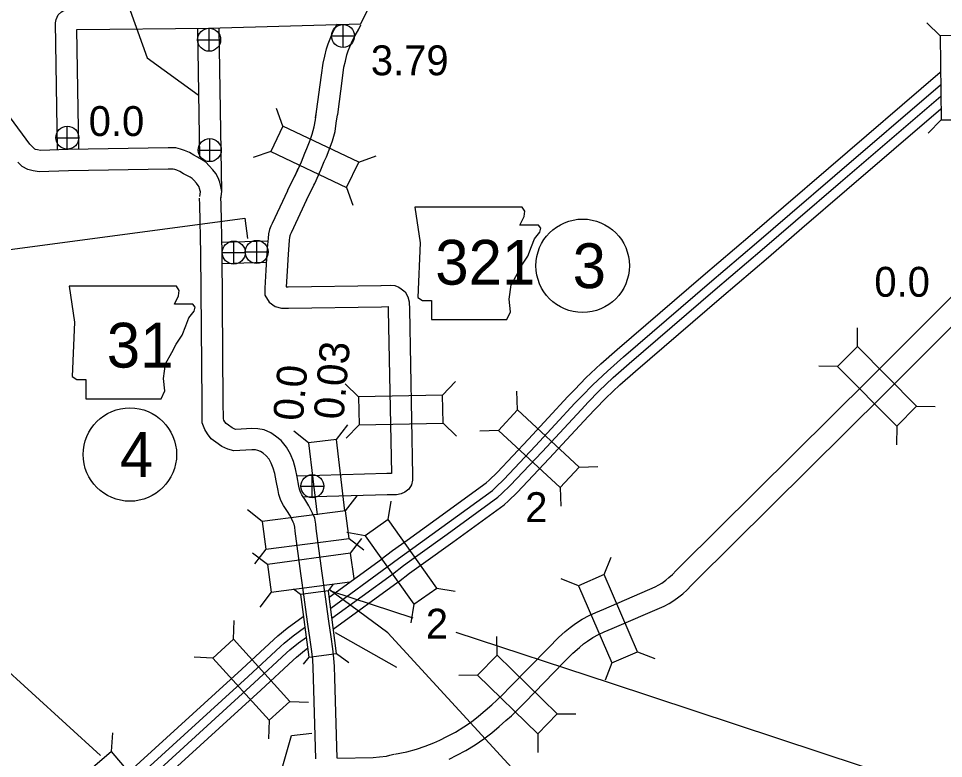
# Model space of a CAD drawing. Extents: x -939622 to -934222, y 1383701 to 1385301.
# Drawn here: x -936410.42 to -936371.19, y 1384450.69 to 1384482.07 of the extents above; entities that cross this region are included whole.
import ezdxf

# ---------------------------------------------------------------- set-up
doc = ezdxf.new("R2010")
doc.units = 0
for name, color, linetype in [('10', 7, 'Continuous'), ('15', 7, 'Continuous'), ('20', 7, 'Continuous'), ('21', 7, 'Continuous'), ('22', 7, 'Continuous'), ('25', 7, 'Continuous'), ('26', 7, 'Continuous'), ('27', 7, 'Continuous')]:
    doc.layers.add(name, color=color, linetype=linetype)

msp = doc.modelspace()

# ---------------------------------------------------------------- linework, layer by layer
at = {"layer": '10'}
for points in [[(-936408.764, 1384476.532), (-936408.845, 1384481.893), (-936408.816, 1384482.034), (-936408.737, 1384482.223), (-936408.59, 1384482.354), (-936408.454, 1384482.435), (-936408.281, 1384482.483), (-936408.107, 1384482.505), (-936402.372, 1384482.567), (-936396.465, 1384482.734), (-936396.297, 1384483.081), (-936396.201, 1384483.299), (-936396.082, 1384483.511), (-936395.97, 1384483.682), (-936395.874, 1384483.83), (-936395.784, 1384483.937)], [(-936407.864, 1384476.559), (-936407.941, 1384481.607), (-936402.355, 1384481.667), (-936395.894, 1384481.85), (-936395.48, 1384482.702), (-936395.394, 1384482.897), (-936395.312, 1384483.044), (-936395.216, 1384483.191), (-936395.15, 1384483.293), (-936395.097, 1384483.355)], [(-936402.723, 1384476.207), (-936402.806, 1384481.616)], [(-936401.801, 1384474.736), (-936401.906, 1384481.644)], [(-936397.816, 1384477.856), (-936397.773, 1384478.133), (-936397.574, 1384479.667), (-936397.502, 1384480.173), (-936397.431, 1384480.473), (-936397.355, 1384480.779), (-936397.279, 1384481.002), (-936397.201, 1384481.204), (-936397.073, 1384481.523), (-936396.921, 1384481.793), (-936396.896, 1384481.836)], [(-936396.886, 1384477.98), (-936396.882, 1384478.005), (-936396.682, 1384479.546), (-936396.616, 1384480.006), (-936396.556, 1384480.261), (-936396.491, 1384480.524), (-936396.432, 1384480.695), (-936396.363, 1384480.875), (-936396.26, 1384481.133), (-936396.141, 1384481.344), (-936395.979, 1384481.618), (-936395.899, 1384481.805)], [(-936401.841, 1384474.406), (-936401.795, 1384474.736), (-936401.831, 1384474.949), (-936401.877, 1384475.127), (-936401.944, 1384475.315), (-936402.049, 1384475.492), (-936402.179, 1384475.66), (-936402.33, 1384475.828), (-936402.475, 1384475.975), (-936402.655, 1384476.098), (-936402.822, 1384476.196), (-936402.985, 1384476.28), (-936403.172, 1384476.387), (-936403.377, 1384476.48), (-936403.544, 1384476.535), (-936403.748, 1384476.584), (-936404.069, 1384476.587), (-936408.318, 1384476.516), (-936409.479, 1384476.473), (-936409.613, 1384476.498), (-936409.704, 1384476.518), (-936409.726, 1384476.53), (-936409.813, 1384476.615), (-936409.932, 1384476.74), (-936410.093, 1384476.96), (-936411.939, 1384479.451)], [(-936398.69, 1384475.404), (-936398.658, 1384475.467), (-936398.42, 1384475.996), (-936398.277, 1384476.367), (-936398.186, 1384476.558), (-936398.051, 1384476.917), (-936397.965, 1384477.164), (-936397.874, 1384477.478), (-936397.829, 1384477.775), (-936397.775, 1384478.12)], [(-936397.886, 1384474.998), (-936397.846, 1384475.079), (-936397.589, 1384475.649), (-936397.449, 1384476.012), (-936397.357, 1384476.205), (-936397.205, 1384476.61), (-936397.107, 1384476.89), (-936396.993, 1384477.285), (-936396.94, 1384477.638), (-936396.886, 1384477.98)], [(-936402.733, 1384474.529), (-936402.706, 1384474.723), (-936402.712, 1384474.761), (-936402.739, 1384474.864), (-936402.763, 1384474.932), (-936402.795, 1384474.986), (-936402.87, 1384475.083), (-936402.984, 1384475.21), (-936403.055, 1384475.28), (-936403.137, 1384475.337), (-936403.256, 1384475.407), (-936403.416, 1384475.489), (-936403.582, 1384475.584), (-936403.705, 1384475.64), (-936403.792, 1384475.669), (-936403.86, 1384475.685), (-936404.066, 1384475.687), (-936408.294, 1384475.616), (-936409.544, 1384475.571), (-936409.79, 1384475.615), (-936410.019, 1384475.666), (-936410.264, 1384475.797), (-936410.454, 1384475.983)], [(-936399.008, 1384474.774), (-936398.658, 1384475.467), (-936398.551, 1384475.705)], [(-936398.205, 1384474.368), (-936397.886, 1384474.998)], [(-936399.014, 1384474.761), (-936399.663, 1384473.374), (-936399.715, 1384473.27), (-936399.774, 1384473.119), (-936399.814, 1384472.94), (-936399.835, 1384472.757), (-936399.867, 1384472.328), (-936399.88, 1384472.136), (-936399.927, 1384471.406), (-936399.966, 1384470.643), (-936399.969, 1384470.339), (-936399.79, 1384470.048), (-936399.534, 1384469.858), (-936399.268, 1384469.794), (-936398.972, 1384469.794), (-936395.03, 1384469.847)], [(-936398.295, 1384457.43), (-936398.441, 1384458.532), (-936398.682, 1384460.326), (-936398.704, 1384460.496), (-936398.725, 1384460.626), (-936398.765, 1384460.72), (-936398.888, 1384460.962), (-936399.043, 1384461.21), (-936399.177, 1384461.419), (-936399.29, 1384461.636), (-936399.376, 1384461.886), (-936399.41, 1384462.063), (-936399.488, 1384462.46), (-936399.554, 1384462.777), (-936399.613, 1384463.005), (-936399.697, 1384463.209), (-936399.794, 1384463.385), (-936399.912, 1384463.528), (-936400.047, 1384463.633), (-936400.16, 1384463.711), (-936400.265, 1384463.757), (-936400.374, 1384463.777), (-936400.523, 1384463.784), (-936401.29, 1384463.744), (-936401.536, 1384463.81), (-936401.799, 1384463.924), (-936402.048, 1384464.102), (-936402.241, 1384464.245), (-936402.404, 1384464.454), (-936402.52, 1384464.646), (-936402.628, 1384464.922), (-936402.634, 1384465.803), (-936402.685, 1384472.112), (-936402.729, 1384474.165), (-936402.737, 1384474.456)], [(-936397.403, 1384457.547), (-936397.549, 1384458.651), (-936397.789, 1384460.443), (-936397.813, 1384460.627), (-936397.855, 1384460.88), (-936397.949, 1384461.101), (-936398.104, 1384461.405), (-936398.281, 1384461.69), (-936398.397, 1384461.871), (-936398.461, 1384461.993), (-936398.504, 1384462.118), (-936398.526, 1384462.234), (-936398.606, 1384462.639), (-936398.677, 1384462.981), (-936398.758, 1384463.291), (-936398.885, 1384463.599), (-936399.046, 1384463.892), (-936399.281, 1384464.178), (-936399.514, 1384464.358), (-936399.718, 1384464.5), (-936400.001, 1384464.624), (-936400.272, 1384464.673), (-936400.525, 1384464.685), (-936401.196, 1384464.65), (-936401.239, 1384464.662), (-936401.353, 1384464.712), (-936401.519, 1384464.83), (-936401.607, 1384464.896), (-936401.661, 1384464.964), (-936401.709, 1384465.044), (-936401.729, 1384465.096), (-936401.734, 1384465.809), (-936401.785, 1384472.126), (-936401.829, 1384474.186), (-936401.837, 1384474.479)], [(-936398.199, 1384474.38), (-936398.852, 1384472.983), (-936398.892, 1384472.904), (-936398.911, 1384472.855), (-936398.925, 1384472.792), (-936398.938, 1384472.673), (-936398.969, 1384472.264), (-936398.982, 1384472.076), (-936399.029, 1384471.354), (-936399.062, 1384470.694), (-936398.978, 1384470.694), (-936395.042, 1384470.747)], [(-936401.779, 1384472.583), (-936399.858, 1384472.64)], [(-936401.775, 1384471.683), (-936399.938, 1384471.737)], [(-936395.052, 1384470.747), (-936394.639, 1384470.762), (-936394.463, 1384470.752), (-936394.293, 1384470.673), (-936394.192, 1384470.61), (-936394.025, 1384470.476), (-936393.905, 1384470.267), (-936393.851, 1384470.057), (-936393.837, 1384469.734), (-936393.702, 1384462.691), (-936393.705, 1384462.488), (-936393.754, 1384462.299), (-936393.867, 1384462.111), (-936394.034, 1384461.992), (-936394.188, 1384461.916), (-936394.39, 1384461.873), (-936394.783, 1384461.876)], [(-936394.469, 1384450.878), (-936393.948, 1384450.975), (-936393.534, 1384451.082), (-936393.167, 1384451.214), (-936392.8, 1384451.357), (-936392.549, 1384451.469), (-936392.254, 1384451.628), (-936391.89, 1384451.816), (-936391.537, 1384452.034), (-936391.206, 1384452.254), (-936390.906, 1384452.486), (-936390.62, 1384452.725), (-936390.344, 1384452.973), (-936390.128, 1384453.164), (-936389.882, 1384453.41), (-936389.578, 1384453.719), (-936387.943, 1384455.392), (-936387.52, 1384455.817), (-936387.227, 1384456.074), (-936387.025, 1384456.254), (-936386.791, 1384456.421), (-936386.514, 1384456.595), (-936386.222, 1384456.758), (-936385.934, 1384456.883), (-936385.59, 1384457.032), (-936383.413, 1384457.974), (-936383.254, 1384458.052), (-936383.129, 1384458.13), (-936382.97, 1384458.25), (-936382.834, 1384458.362), (-936382.683, 1384458.5), (-936382.523, 1384458.658), (-936382.354, 1384458.832), (-936374.322, 1384466.793), (-936370.847, 1384470.269)], [(-936395.019, 1384469.848), (-936394.743, 1384469.857), (-936394.737, 1384469.707), (-936394.604, 1384462.775), (-936394.776, 1384462.776)], [(-936392.153, 1384450.66), (-936391.833, 1384450.832), (-936391.446, 1384451.033), (-936391.051, 1384451.276), (-936390.681, 1384451.522), (-936390.342, 1384451.785), (-936390.031, 1384452.045), (-936389.745, 1384452.301), (-936389.511, 1384452.508), (-936389.243, 1384452.776), (-936388.936, 1384453.088), (-936387.302, 1384454.76), (-936386.904, 1384455.16), (-936386.63, 1384455.401), (-936386.462, 1384455.55), (-936386.291, 1384455.673), (-936386.056, 1384455.82), (-936385.822, 1384455.95), (-936385.576, 1384456.057), (-936385.233, 1384456.206), (-936383.036, 1384457.156), (-936382.817, 1384457.264), (-936382.618, 1384457.388), (-936382.413, 1384457.543), (-936382.244, 1384457.681), (-936382.062, 1384457.848), (-936381.884, 1384458.024), (-936381.715, 1384458.198), (-936373.687, 1384466.156), (-936370.208, 1384469.636)], [(-936394.792, 1384462.776), (-936398.586, 1384462.669)], [(-936394.767, 1384461.876), (-936398.37, 1384461.775)], [(-936396.896, 1384450.707), (-936395.372, 1384450.733), (-936395.102, 1384450.757), (-936394.815, 1384450.792), (-936394.67, 1384450.828), (-936394.497, 1384450.872)]]:
    msp.add_lwpolyline(points, dxfattribs=at)
at = {"layer": '15'}
for points in [[(-936376.062, 1384475.732), (-936371.325, 1384479.792)], [(-936375.793, 1384475.419), (-936371.313, 1384479.259)], [(-936375.549, 1384475.134), (-936371.295, 1384478.781)], [(-936375.281, 1384474.821), (-936371.297, 1384478.236)], [(-936395.036, 1384459.141), (-936394.553, 1384459.511), (-936393.935, 1384459.949), (-936392.701, 1384460.841), (-936390.581, 1384462.385), (-936390.452, 1384462.499), (-936390.124, 1384462.819), (-936388.787, 1384464.237), (-936387.118, 1384466.038), (-936386.82, 1384466.345), (-936386.357, 1384466.828), (-936385.721, 1384467.427), (-936385.029, 1384468.031), (-936381.377, 1384471.173), (-936379.392, 1384472.869), (-936377.971, 1384474.089), (-936376.063, 1384475.731)], [(-936394.785, 1384458.814), (-936394.308, 1384459.179), (-936393.695, 1384459.614), (-936392.459, 1384460.507), (-936390.322, 1384462.063), (-936390.171, 1384462.197), (-936389.83, 1384462.53), (-936388.486, 1384463.956), (-936386.818, 1384465.754), (-936386.523, 1384466.058), (-936386.066, 1384466.535), (-936385.444, 1384467.122), (-936384.759, 1384467.719), (-936381.109, 1384470.86), (-936379.124, 1384472.556), (-936377.702, 1384473.777), (-936375.794, 1384475.418)], [(-936394.556, 1384458.516), (-936394.086, 1384458.877), (-936393.477, 1384459.309), (-936392.239, 1384460.203), (-936390.086, 1384461.771), (-936389.915, 1384461.923), (-936389.562, 1384462.267), (-936388.212, 1384463.7), (-936386.546, 1384465.496), (-936386.253, 1384465.798), (-936385.802, 1384466.269), (-936385.192, 1384466.844), (-936384.513, 1384467.436), (-936380.865, 1384470.576), (-936378.88, 1384472.271), (-936377.457, 1384473.492), (-936375.549, 1384475.134)], [(-936394.305, 1384458.189), (-936393.841, 1384458.545), (-936393.237, 1384458.973), (-936391.996, 1384459.869), (-936389.827, 1384461.449), (-936389.634, 1384461.621), (-936389.268, 1384461.977), (-936387.911, 1384463.418), (-936386.247, 1384465.212), (-936385.956, 1384465.512), (-936385.511, 1384465.976), (-936384.915, 1384466.538), (-936384.243, 1384467.124), (-936380.596, 1384470.262), (-936378.612, 1384471.957), (-936377.189, 1384473.179), (-936375.28, 1384474.822)], [(-936397.241, 1384457.533), (-936395.024, 1384459.15)], [(-936397.177, 1384457.069), (-936394.781, 1384458.816)], [(-936397.132, 1384456.638), (-936394.56, 1384458.513)], [(-936397.066, 1384456.175), (-936394.317, 1384458.18)], [(-936397.804, 1384450.675), (-936397.9, 1384454.089), (-936397.915, 1384454.55), (-936397.94, 1384454.874), (-936397.976, 1384455.235), (-936398.047, 1384455.728), (-936398.142, 1384456.393), (-936398.294, 1384457.423)], [(-936396.905, 1384450.702), (-936397.001, 1384454.116), (-936397.016, 1384454.6), (-936397.044, 1384454.953), (-936397.082, 1384455.343), (-936397.156, 1384455.857), (-936397.252, 1384456.523), (-936397.404, 1384457.554)], [(-936405.74, 1384450.113), (-936400.95, 1384454.474), (-936399.584, 1384455.745), (-936399.424, 1384455.894), (-936399.025, 1384456.22), (-936398.35, 1384456.72)], [(-936405.473, 1384449.798), (-936400.671, 1384454.171), (-936399.303, 1384455.443), (-936399.153, 1384455.583), (-936398.771, 1384455.894), (-936398.288, 1384456.253)], [(-936405.23, 1384449.512), (-936400.417, 1384453.895), (-936399.048, 1384455.168), (-936398.906, 1384455.3), (-936398.541, 1384455.598), (-936398.211, 1384455.843)], [(-936404.963, 1384449.198), (-936400.137, 1384453.591), (-936398.767, 1384454.866), (-936398.635, 1384454.989), (-936398.288, 1384455.273), (-936398.16, 1384455.367)]]:
    msp.add_lwpolyline(points, dxfattribs=at)
at = {"layer": '20'}
for p, q in [((-936371.326, 1384481.333), (-936371.892, 1384481.887)), ((-936399.208, 1384477.51), (-936399.472, 1384478.257)), ((-936371.288, 1384477.769), (-936371.843, 1384477.203)), ((-936399.719, 1384476.438), (-936400.466, 1384476.173)), ((-936395.991, 1384475.976), (-936395.244, 1384476.241)), ((-936396.502, 1384474.904), (-936396.237, 1384474.158)), ((-936374.837, 1384468.158), (-936374.834, 1384468.95)), ((-936375.681, 1384467.322), (-936376.473, 1384467.325)), ((-936395.999, 1384466.035), (-936396.569, 1384466.584)), ((-936392.435, 1384466.103), (-936391.886, 1384466.674)), ((-936389.252, 1384465.475), (-936389.281, 1384466.266)), ((-936372.328, 1384465.627), (-936371.536, 1384465.624)), ((-936396.936, 1384464.222), (-936396.446, 1384464.844)), ((-936395.976, 1384464.847), (-936396.525, 1384464.276)), ((-936392.413, 1384464.916), (-936391.842, 1384464.367)), ((-936373.172, 1384464.791), (-936373.175, 1384463.999)), ((-936398.116, 1384464.083), (-936398.738, 1384464.574)), ((-936390.059, 1384464.604), (-936390.851, 1384464.574)), ((-936396.936, 1384464.222), (-936398.116, 1384464.083)), ((-936398.116, 1384464.083), (-936397.756, 1384461.03)), ((-936396.579, 1384461.191), (-936396.936, 1384464.222)), ((-936386.638, 1384463.052), (-936385.847, 1384463.081)), ((-936387.446, 1384462.18), (-936387.416, 1384461.389)), ((-936396.543, 1384461.199), (-936396.058, 1384461.825)), ((-936394.743, 1384460.825), (-936394.61, 1384461.606)), ((-936400.078, 1384460.748), (-936400.705, 1384461.233)), ((-936395.712, 1384460.138), (-936396.493, 1384460.272)), ((-936396.332, 1384459.393), (-936395.852, 1384460.023)), ((-936396.393, 1384460.02), (-936395.767, 1384459.536)), ((-936399.864, 1384458.919), (-936400.494, 1384459.399)), ((-936399.928, 1384459.57), (-936400.413, 1384458.943)), ((-936396.332, 1384459.393), (-936399.864, 1384458.919)), ((-936396.188, 1384458.322), (-936396.332, 1384459.393)), ((-936399.864, 1384458.919), (-936399.706, 1384457.741)), ((-936385.573, 1384458.49), (-936385.282, 1384459.226)), ((-936399.706, 1384457.741), (-936396.368, 1384458.19)), ((-936397.277, 1384457.797), (-936397.053, 1384458.089)), ((-936386.664, 1384458.019), (-936387.4, 1384458.31)), ((-936399.706, 1384457.741), (-936400.186, 1384457.111)), ((-936398.454, 1384457.641), (-936398.756, 1384457.871)), ((-936397.277, 1384457.797), (-936398.454, 1384457.641)), ((-936396.926, 1384455.152), (-936397.276, 1384457.788)), ((-936394.754, 1384456.017), (-936397.242, 1384457.857)), ((-936392.682, 1384457.917), (-936391.902, 1384457.784)), ((-936398.455, 1384457.644), (-936398.103, 1384454.989)), ((-936393.652, 1384457.23), (-936393.785, 1384456.45)), ((-936401.304, 1384455.75), (-936401.267, 1384456.542)), ((-936394.375, 1384454.557), (-936396.972, 1384456.017)), ((-936390.117, 1384455.073), (-936390.126, 1384455.865)), ((-936402.183, 1384454.951), (-936402.974, 1384454.988)), ((-936398.104, 1384454.995), (-936398.339, 1384454.688)), ((-936398.104, 1384454.995), (-936396.926, 1384455.151)), ((-936396.926, 1384455.151), (-936396.415, 1384454.76)), ((-936384.159, 1384455.219), (-936383.423, 1384454.927)), ((-936385.25, 1384454.747), (-936385.542, 1384454.011)), ((-936390.947, 1384454.224), (-936391.739, 1384454.214)), ((-936398.905, 1384453.115), (-936398.114, 1384453.078)), ((-936387.567, 1384452.583), (-936386.775, 1384452.592)), ((-936399.783, 1384452.315), (-936399.82, 1384451.524)), ((-936406.48, 1384450.985), (-936406.415, 1384451.774)), ((-936388.397, 1384451.733), (-936388.388, 1384450.941))]:
    msp.add_line(p, q, dxfattribs=at)
for points in [[(-936371.326, 1384481.333), (-936371.288, 1384477.769), (-936370.1, 1384477.781), (-936370.138, 1384481.345)], [(-936395.991, 1384475.976), (-936399.208, 1384477.51), (-936399.719, 1384476.438), (-936396.502, 1384474.904)], [(-936375.681, 1384467.322), (-936373.172, 1384464.791), (-936372.328, 1384465.627), (-936374.837, 1384468.158)], [(-936392.435, 1384466.103), (-936395.999, 1384466.035), (-936395.976, 1384464.847), (-936392.413, 1384464.916)], [(-936386.638, 1384463.052), (-936389.252, 1384465.475), (-936390.059, 1384464.604), (-936387.446, 1384462.18)], [(-936396.543, 1384461.199), (-936400.078, 1384460.748), (-936399.928, 1384459.57), (-936396.393, 1384460.02)], [(-936392.682, 1384457.917), (-936394.743, 1384460.825), (-936395.712, 1384460.138), (-936393.652, 1384457.23)], [(-936386.664, 1384458.019), (-936385.25, 1384454.747), (-936384.159, 1384455.219), (-936385.573, 1384458.49)], [(-936402.183, 1384454.951), (-936399.783, 1384452.315), (-936398.905, 1384453.115), (-936401.304, 1384455.75)], [(-936387.567, 1384452.583), (-936390.117, 1384455.073), (-936390.947, 1384454.224), (-936388.397, 1384451.733)]]:
    msp.add_lwpolyline(points, close=True, dxfattribs=at)
msp.add_lwpolyline([(-936404.203, 1384448.303), (-936406.48, 1384450.985), (-936407.386, 1384450.216), (-936405.128, 1384447.556)], dxfattribs=at)
at = {"layer": '21'}
for p, q in [((-936406.208, 1384483.862), (-936404.964, 1384480.4)), ((-936404.964, 1384480.4), (-936402.8, 1384478.831)), ((-936411.692, 1384472.151), (-936400.819, 1384473.611)), ((-936400.819, 1384473.611), (-936400.711, 1384472.746)), ((-936406.936, 1384450.816), (-936418.073, 1384460.942))]:
    msp.add_line(p, q, dxfattribs=at)
for points in [[(-936393.615, 1384474.075), (-936393.387, 1384472.552), (-936393.489, 1384470.243), (-936393.286, 1384470.116), (-936392.905, 1384470.116), (-936392.905, 1384469.304), (-936389.707, 1384469.304), (-936389.555, 1384469.634), (-936389.606, 1384470.167), (-936389.53, 1384470.776), (-936389.251, 1384471.258), (-936389.073, 1384471.613), (-936388.819, 1384471.994), (-936388.667, 1384472.4), (-936388.54, 1384472.73), (-936388.312, 1384473.009), (-936388.261, 1384473.187), (-936388.362, 1384473.313), (-936389.149, 1384473.313), (-936388.971, 1384473.669), (-936388.946, 1384473.897), (-936389.051, 1384474.072)], [(-936408.275, 1384470.721), (-936408.046, 1384469.198), (-936408.148, 1384466.889), (-936407.945, 1384466.762), (-936407.564, 1384466.762), (-936407.564, 1384465.95), (-936404.367, 1384465.95), (-936404.214, 1384466.28), (-936404.265, 1384466.813), (-936404.189, 1384467.422), (-936403.91, 1384467.904), (-936403.732, 1384468.259), (-936403.479, 1384468.64), (-936403.326, 1384469.046), (-936403.199, 1384469.376), (-936402.971, 1384469.655), (-936402.92, 1384469.833), (-936403.022, 1384469.96), (-936403.808, 1384469.96), (-936403.631, 1384470.315), (-936403.605, 1384470.543), (-936403.711, 1384470.719)]]:
    msp.add_lwpolyline(points, close=True, dxfattribs=at)
at = {"layer": '22'}
for p, q in [((-936400.473, 1384446.002), (-936398.838, 1384451.663)), ((-936398.838, 1384451.663), (-936397.972, 1384451.771))]:
    msp.add_line(p, q, dxfattribs=at)
at = {"layer": '25'}
for p, q in [((-936397.277, 1384457.797), (-936397.053, 1384458.089)), ((-936394.754, 1384456.017), (-936397.242, 1384457.857)), ((-936397.188, 1384457.802), (-936393.695, 1384456.652)), ((-936389.182, 1384449.959), (-936394.754, 1384456.017)), ((-936391.875, 1384456.052), (-936385.327, 1384453.896)), ((-936385.327, 1384453.896), (-936372.834, 1384449.78))]:
    msp.add_line(p, q, dxfattribs=at)
at = {"layer": '26'}
for p, q in [((-936402.333, 1384480.683), (-936402.333, 1384481.658)), ((-936396.653, 1384480.845), (-936396.653, 1384481.82)), ((-936397.14, 1384481.332), (-936396.165, 1384481.332)), ((-936402.82, 1384481.17), (-936401.845, 1384481.17)), ((-936408.35, 1384476.531), (-936408.35, 1384477.506)), ((-936408.838, 1384477.018), (-936407.863, 1384477.018)), ((-936402.306, 1384476.004), (-936402.306, 1384476.979)), ((-936402.793, 1384476.491), (-936401.818, 1384476.491)), ((-936401.288, 1384471.659), (-936401.288, 1384472.634)), ((-936400.314, 1384471.686), (-936400.314, 1384472.661)), ((-936401.775, 1384472.147), (-936400.8, 1384472.147)), ((-936400.802, 1384472.174), (-936399.827, 1384472.174)), ((-936397.959, 1384461.751), (-936397.959, 1384462.726)), ((-936398.446, 1384462.239), (-936397.471, 1384462.239))]:
    msp.add_line(p, q, dxfattribs=at)
for centre in [(-936402.333, 1384481.17), (-936396.653, 1384481.332), (-936408.35, 1384477.018), (-936402.306, 1384476.491), (-936401.288, 1384472.147), (-936400.314, 1384472.174), (-936397.959, 1384462.239)]:
    msp.add_circle(centre, 0.487, dxfattribs=at)
at = {"layer": '27'}
for centre in [(-936386.491, 1384471.587), (-936405.694, 1384463.581)]:
    msp.add_circle(centre, 1.98, dxfattribs=at)

# ---------------------------------------------------------------- texts
at = {"layer": '20'}
for p in [(-936388.928, 1384460.717), (-936393.143, 1384455.776)]:
    msp.add_text('2', height=1.267, dxfattribs=at).set_placement(p)
at = {"layer": '21'}
for s, p in [('321', (-936392.742, 1384470.784)), ('31', (-936406.674, 1384467.268))]:
    msp.add_text(s, height=1.9008, dxfattribs=at).set_placement(p)
at = {"layer": '25'}
for s, p in [('3.79', (-936395.475, 1384479.664)), ('0.0', (-936407.441, 1384477.089)), ('0.0', (-936374.119, 1384470.273))]:
    msp.add_text(s, height=1.2672, dxfattribs=at).set_placement(p)
for s, p in [('0.03', (-936396.641, 1384465.033)), ('0.0', (-936398.363, 1384464.976))]:
    msp.add_text(s, height=1.2672, rotation=85, dxfattribs=at).set_placement(p)
at = {"layer": '27'}
for s, p in [('3', (-936386.916, 1384470.637)), ('4', (-936406.119, 1384462.631))]:
    msp.add_text(s, height=1.901, dxfattribs=at).set_placement(p)

doc.saveas('drawing.dxf')
